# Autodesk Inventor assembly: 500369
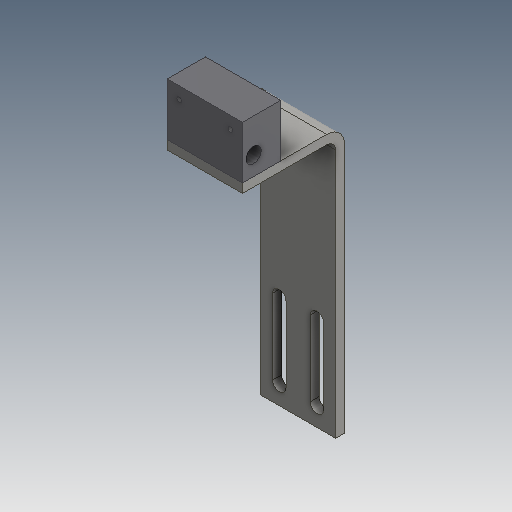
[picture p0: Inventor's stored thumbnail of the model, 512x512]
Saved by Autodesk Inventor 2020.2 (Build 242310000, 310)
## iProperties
Created: 1999-12
Part Number: 500369
Description: WMT-CP,FH,XX,MNT,PLOW
Document SubType Name: Assembly
Designer: sspink
Mass: 379.435 g
Surface Area: 361.467 cm^2
Volume: 104.723 cm^3
Density: 3.62322 g/cm^3
Control State: 0
Checked Out: False
Master: False
Shininess: 0.0
Length Units: 11269
Angle Units: 11279
Time Units: 11290
Mass Units: 11283
Length Display Precision: 3
Angle Display Precision: 2
Compacted: True
Dimensions: 212,9x68x50 mm
Mass: 0,379 kg
Density: 0.0
Volumn: 0.0
Area: 0.0
PropertySet Name: Model Information
Author: sspink
Revision Number: -
Title: WMT-CP,FH,XX,MNT,PLOW
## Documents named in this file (3)
- D:\07 - DEMODATEN\OTX 2019 - Dataset - UPDATE - Dez2019\Designs\07-Packing machine\500369.iam
- D:\07 - DEMODATEN\OTX 2019 - Dataset - UPDATE - Dez2019\Designs\07-Packing machine\Parts\ADSK-011352.ipt
- D:\07 - DEMODATEN\OTX 2019 - Dataset - UPDATE - Dez2019\Designs\07-Packing machine\Parts\ADSK-011351.ipt
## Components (2 placed, 2 different names)
1. ADSK-011351:1 — Mate:1, Flush:1, Flush:2
2. ADSK-011352:1 — Mate:1, Flush:1, Flush:2, Flush:3, Flush:4, Flush:5
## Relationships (6: Flush 5, Mate 1)
- Mate:1: ADSK-011351:1 ↔ ADSK-011352:1
- Flush:1: ADSK-011351:1 ↔ ADSK-011352:1
- Flush:2: ADSK-011351:1 ↔ ADSK-011352:1
- Flush:3: ADSK-011352:1
- Flush:4: ADSK-011352:1
- Flush:5: ADSK-011352:1
